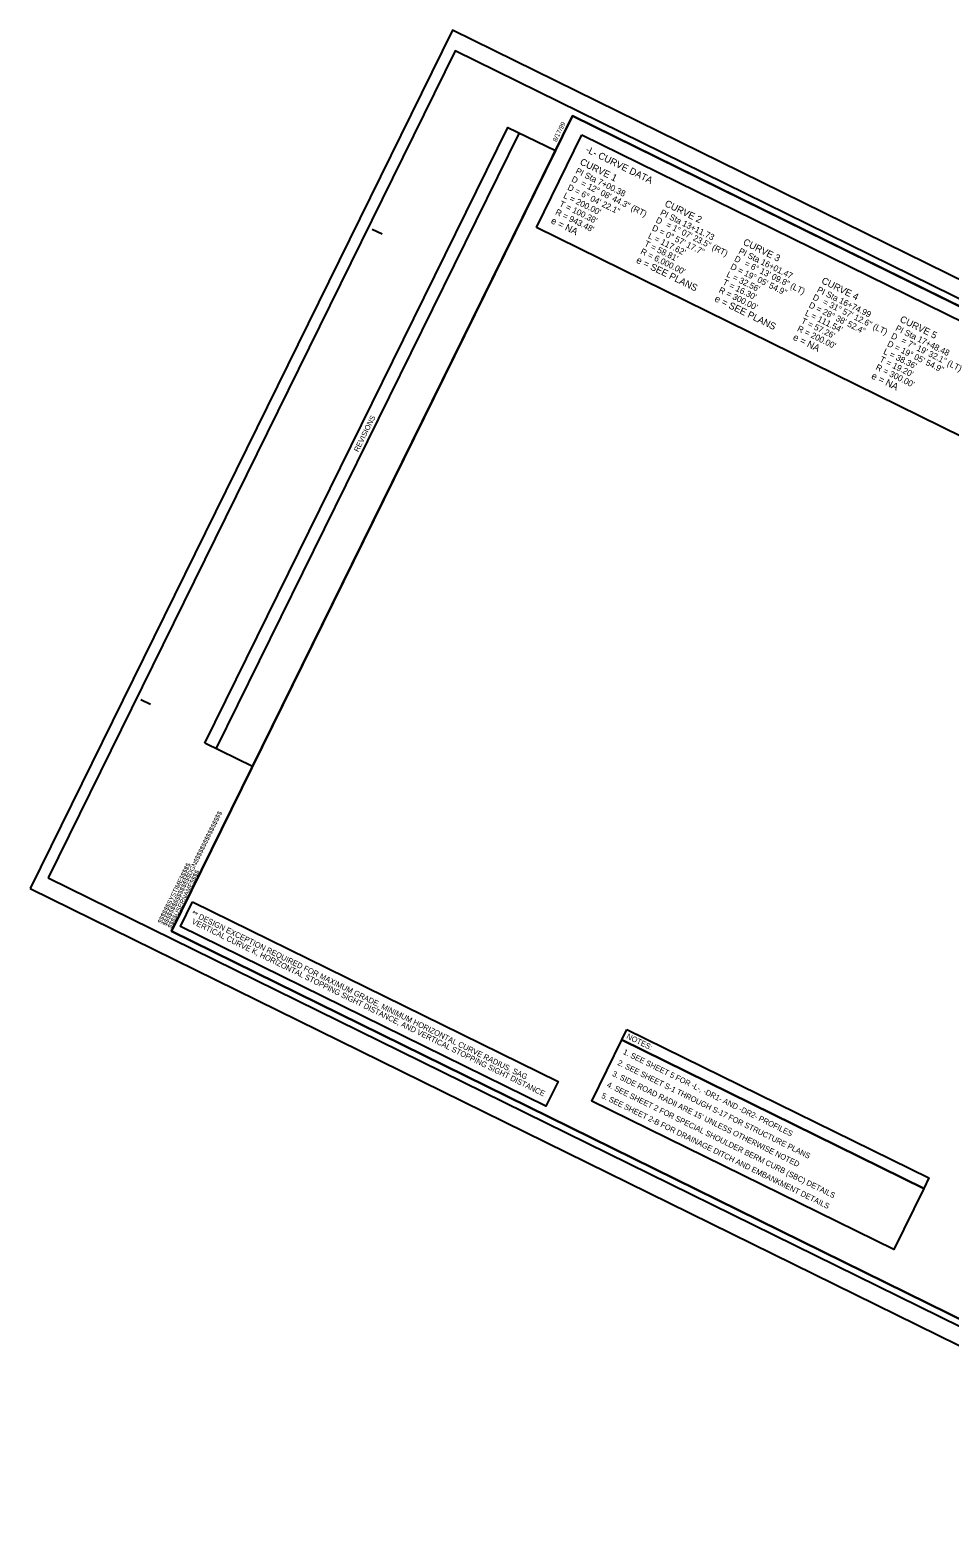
# Model space of a CAD drawing. Extents: x 1428420 to 1430540, y 857897 to 859622.
# Drawn here: x 1428420 to 1429472, y 857897 to 859622 of the extents above; entities that cross this region are included whole.
import ezdxf

# ---------------------------------------------------------------- set-up
doc = ezdxf.new("R2010")
doc.units = 0
for name, color, linetype in [('Old_Level_51', 7, 'Continuous'), ('Prop Grid Mask', 7, 'Continuous'), ('Prop Horizontal Alignment Curve and Spiral Data', 7, 'Continuous'), ('Prop Horizontal Alignment Station Label', 7, 'Continuous'), ('Sheet Block Revision CELL', 7, 'Continuous'), ('Sheet Data Field CELL', 7, 'Continuous'), ('Sheet Plan CELL', 7, 'Continuous'), ('Sheet Plot Border Inside CELL', 7, 'Continuous'), ('Sheet Plot Border Outside CELL', 7, 'Continuous')]:
    doc.layers.add(name, color=color, linetype=linetype)

msp = doc.modelspace()

# ---------------------------------------------------------------- linework, layer by layer
at = {"layer": 'Prop Grid Mask'}
for points in [[(1428605.9, 858624.8), (1429024.1, 858419), (1429010.2, 858390.8), (1428592.1, 858596.6)], [(1429103, 858478.6), (1429448.5, 858308.6), (1429442.6, 858296.6), (1429097.1, 858466.6)], [(1429097.1, 858466.6), (1429442.6, 858296.6), (1429408.2, 858226.7), (1429062.7, 858396.7)]]:
    msp.add_lwpolyline(points, close=True, dxfattribs=at)
at = {"layer": 'Prop Horizontal Alignment Curve and Spiral Data'}
for p, q in [((1428999.3, 859396.5), (1429051.5, 859502.6)), ((1429051.5, 859502.6), (1429609.8, 859227.9)), ((1429557.6, 859121.8), (1428999.3, 859396.5))]:
    msp.add_line(p, q, dxfattribs=at)
at = {"layer": 'Sheet Block Revision CELL'}
msp.add_line((1428633, 858799.8), (1428979.9, 859504.8), dxfattribs=at)
msp.add_lwpolyline([(1428620, 858806.2), (1428966.8, 859511.2), (1429021.2, 859484.5), (1428674.3, 858779.5)], close=True, dxfattribs=at)
at = {"layer": 'Sheet Plan CELL'}
for p, q in [((1429040.7, 859524.3), (1429040.7, 859524.3)), ((1428811.5, 859394.7), (1428822.7, 859389.2)), ((1428546.6, 858856.3), (1428557.8, 858850.8)), ((1428581.6, 858591.1), (1428581.6, 858591.1))]:
    msp.add_line(p, q, dxfattribs=at)
for points in [[(1430386.7, 858862), (1429040.7, 859524.3), (1428581.6, 858591.1), (1429927.5, 857928.9)], [(1428581.6, 858591.1), (1429040.7, 859524.3), (1430207.2, 858950.3), (1430140.9, 858815.7), (1430320.4, 858727.4), (1429927.5, 857928.9)]]:
    msp.add_lwpolyline(points, close=True, dxfattribs=at)
at = {"layer": 'Sheet Plot Border Inside CELL'}
msp.add_lwpolyline([(1428440.5, 858652.1), (1429935.4, 857916.6), (1430401.2, 858863.2), (1428906.3, 859598.8)], close=True, dxfattribs=at)
at = {"layer": 'Sheet Plot Border Outside CELL'}
msp.add_lwpolyline([(1428420.1, 858639.9), (1429930.6, 857896.7), (1430414, 858879.2), (1428903.5, 859622.4)], close=True, dxfattribs=at)

# ---------------------------------------------------------------- texts
at = {"layer": 'Old_Level_51'}
for s, p in [('1. SEE SHEET 5 FOR -L-, -DR1- AND -DR2- PROFILES', (1429097.8, 858450.8)), ('2. SEE SHEET S-1 THROUGH S-17 FOR STRUCTURE PLANS', (1429091.6, 858438.3)), ('4. SEE SHEET 2 FOR SPECIAL SHOULDER BERM CURB (SBC) DETAILS', (1429079.3, 858413.2)), ("3. SIDE ROAD RADII ARE 15' UNLESS OTHERWISE NOTED", (1429085.5, 858425.8)), ('5. SEE SHEET 2-B FOR DRAINAGE DITCH AND EMBANKMENT DETAILS', (1429073.1, 858400.7))]:
    msp.add_text(s, height=6.375, rotation=333.8001, dxfattribs=at).set_placement(p)
at = {"layer": 'Prop Horizontal Alignment Curve and Spiral Data'}
for s, height, rotation, p in [('-L- CURVE DATA', 7.875, 333.7014, (1429055, 859483.3)), ('-L- CURVE DATA', 7.875, 333.7014, (1429055, 859483.3)), ('CURVE 1', 7.87, 333.7014, (1429048.4, 859469.1)), ('D', 7, 333.7997, (1429038.8, 859449.6)), ('PI Sta 7+00.38', 7, 333.7997, (1429043.5, 859459)), ("L = 200.00'", 7, 333.7997, (1429029.6, 859430.8)), ('D = 6%%d 04\' 22.1"', 7, 333.7997, (1429034.2, 859440.2)), ('= 12%%d 08\' 44.3" (RT)', 7, 333.7997, (1429049.6, 859444.8)), ("R = 943.48'", 7, 333.7997, (1429020.3, 859411.9)), ("T = 100.38'", 7, 333.7997, (1429024.9, 859421.3)), ('PI Sta 13+11.73', 7, 333.8095, (1429140.4, 859411.3)), ('CURVE 2', 7.87, 333.7014, (1429145.4, 859421.4)), ('e = NA', 7.88, 333.9546, (1429015.3, 859401.8)), ('D = 0%%d 57\' 17.7"', 7, 333.8095, (1429130.9, 859393.7)), ('D', 7, 333.8095, (1429135.3, 859402.7)), ('= 1%%d 07\' 23.5" (RT)', 7, 333.8095, (1429147, 859397.3)), ("L = 117.62'", 7, 333.8095, (1429126.5, 859384.7)), ('CURVE 3', 7.87, 333.7014, (1429235.1, 859377.3)), ("R = 6,000.00'", 7, 333.8095, (1429117.7, 859366.8)), ("T = 58.81'", 7, 333.8095, (1429122.1, 859375.7)), ('PI Sta 16+01.47', 7, 333.8095, (1429230.1, 859367.2)), ('e = SEE PLANS', 7.875, 333.9546, (1429112.8, 859356.7)), ('D = 19%%d 05\' 54.9"', 7, 333.8095, (1429220.7, 859349.5)), ('D', 7, 333.8095, (1429225.1, 859358.5)), ('= 6%%d 13\' 09.8" (LT)', 7, 333.8095, (1429236.7, 859353.1)), ("T = 16.30'", 7, 333.8095, (1429211.8, 859331.6)), ("L = 32.56'", 7, 333.8095, (1429216.2, 859340.6)), ('CURVE 4', 7.87, 333.7014, (1429324.8, 859333.1)), ('e = SEE PLANS', 7.875, 333.9546, (1429202.5, 859312.5)), ("R = 300.00'", 7, 333.8095, (1429207.4, 859322.6)), ('D', 7, 333.8095, (1429314.8, 859314.4)), ('PI Sta 16+74.99', 7, 333.8095, (1429319.8, 859323)), ('= 31%%d 57\' 12.6" (LT)', 7, 333.8095, (1429326.5, 859309)), ("L = 111.54'", 7, 333.8095, (1429306, 859296.4)), ('D = 28%%d 38\' 52.4"', 7, 333.8095, (1429310.4, 859305.4)), ("R = 200.00'", 7, 333.8095, (1429297.1, 859278.5)), ("T = 57.26'", 7, 333.8095, (1429301.6, 859287.4)), ('PI Sta 17+48.48', 7, 333.8095, (1429409.5, 859278.9)), ('CURVE 5', 7.87, 333.7014, (1429414.5, 859289)), ('e = NA', 7.88, 333.9546, (1429292.2, 859268.4)), ('D = 19%%d 05\' 54.9"', 7, 333.8095, (1429400.1, 859261.2)), ('D', 7, 333.8095, (1429404.5, 859270.2)), ('= 7%%d 19\' 32.1" (LT)', 7, 333.8095, (1429416.2, 859264.8)), ("T = 19.20'", 7, 333.8095, (1429391.3, 859243.3)), ("L = 38.36'", 7, 333.8095, (1429395.7, 859252.3)), ('e = NA', 7.88, 333.9546, (1429381.9, 859224.2)), ("R = 300.00'", 7, 333.8095, (1429386.9, 859234.3))]:
    msp.add_text(s, height=height, rotation=rotation, dxfattribs=at).set_placement(p)
at = {"layer": 'Prop Horizontal Alignment Station Label'}
msp.add_text('NOTES:', height=6.37, rotation=333.8001, dxfattribs=at).set_placement((1429101.8, 858468.6))
at = {"layer": 'Sheet Block Revision CELL'}
msp.add_text('REVISIONS', height=6, rotation=63.8001, dxfattribs=at).set_placement((1428795.5, 859139.1))
at = {"layer": 'Sheet Data Field CELL'}
for s, p in [('** DESIGN EXCEPTION REQUIRED FOR MAXIMUM GRADE, MINIMUM HORIZONTAL CURVE RADIUS, SAG', (1428603.9, 858609.6)), ('  VERTICAL CURVE K, HORIZONTAL STOPPING SIGHT DISTANCE, AND VERTICAL STOPPING SIGHT DISTANCE', (1428600.2, 858602.1))]:
    msp.add_text(s, height=6.375, rotation=333.8001, dxfattribs=at).set_placement(p)
at = {"layer": 'Sheet Plan CELL'}
for s, p in [('8/17/99', (1429022.3, 859494.1)), ('$$$$$$$$$$$$$$$$DGN$$$$$$$$$$$$$$$$', (1428575.8, 858596.6)), ('$$$$$$SYSTIME$$$$$', (1428570.3, 858599.3)), ('$$$$USERNAME$$$$', (1428581.7, 858593.7))]:
    msp.add_text(s, height=5.25, rotation=63.8001, dxfattribs=at).set_placement(p)

doc.saveas('drawing.dxf')
